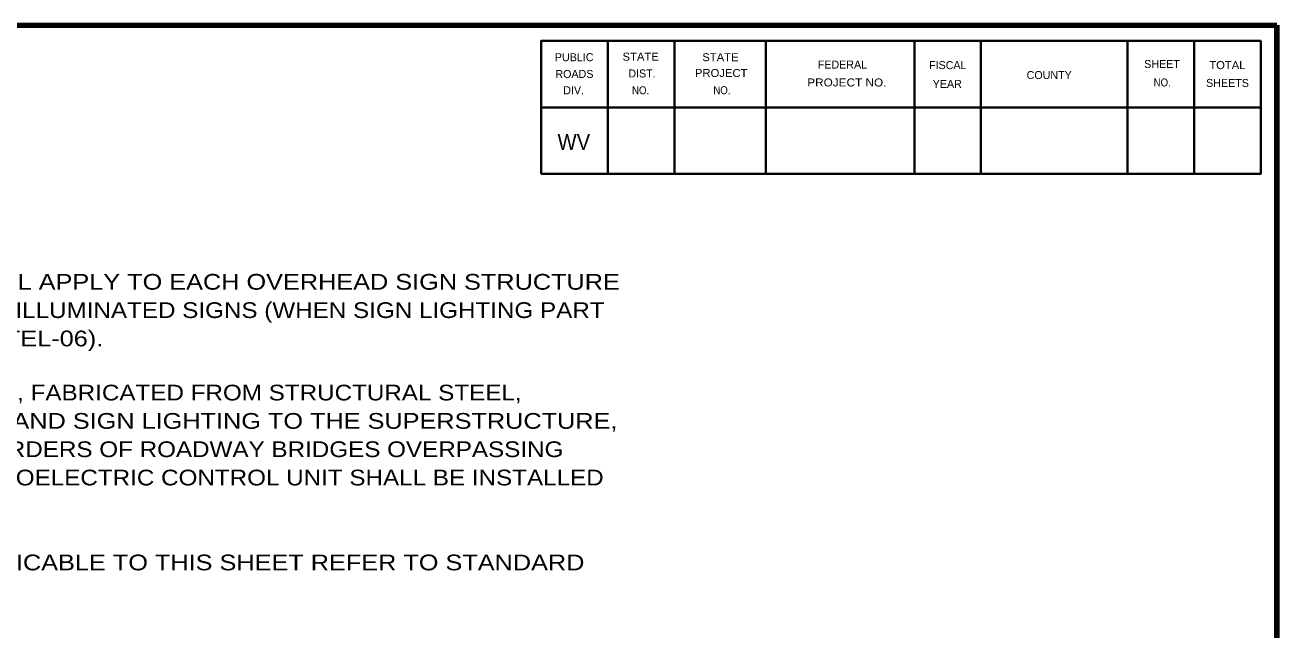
# Model space of a CAD drawing. Extents: x -111 to 744, y -77 to 467.
# Drawn here: x 499.2 to 737.7, y 344.9 to 460.3 of the extents above; entities that cross this region are included whole.
import ezdxf

# ---------------------------------------------------------------- set-up
doc = ezdxf.new("R2010")
doc.units = 0
doc.header["$LTSCALE"] = 1.2
doc.layers.add('1', color=7, linetype='Continuous', lineweight=53)
doc.layers.add('61', color=7, linetype='Continuous', lineweight=35)

msp = doc.modelspace()

# ---------------------------------------------------------------- linework, layer by layer
at = {"layer": '1', "lineweight": 158}
msp.add_line((737.728, -65.835), (737.728, 460.265), dxfattribs=at)
at = {"layer": '1', "lineweight": 13}
msp.add_line((737.728, -65.835), (737.728, 460.265), dxfattribs=at)
at = {"layer": '1', "lineweight": 158}
msp.add_lwpolyline([(737.728, 460.265), (-53.972, 460.165), (-53.872, -65.835)], dxfattribs=at)
at = {"layer": '61'}
for p, q in [((610.228, 457.265), (610.228, 431.865)), ((622.928, 457.265), (622.928, 431.865)), ((640.328, 457.265), (640.328, 431.865)), ((668.628, 457.265), (668.628, 431.865)), ((681.328, 457.265), (681.328, 431.865)), ((709.228, 457.265), (709.228, 431.865)), ((721.928, 457.265), (721.928, 431.865)), ((734.628, 444.565), (597.528, 444.565))]:
    msp.add_line(p, q, dxfattribs=at)
for points in [[(734.628, 457.265), (597.528, 457.265), (597.528, 431.865)], [(734.628, 457.265), (734.628, 431.865), (597.528, 431.865)]]:
    msp.add_lwpolyline(points, dxfattribs=at)

# ---------------------------------------------------------------- texts
at = {"layer": '1'}
for s, height, width, p in [('WV', 3.048, 0.95, (600.628, 436.465)), ('DETAILS OF THIS SHEET SHALL APPLY TO EACH OVERHEAD SIGN STRUCTURE', 3, 1.2, (426.063, 409.807)), ('THAT SUPPORTS EXTERNALLY ILLUMINATED SIGNS (WHEN SIGN LIGHTING PART', 3, 1.15, (426.063, 404.407)), ('OF ROADWAY LIGHTING SEE TEL-06).', 3, 1.2, (426.063, 399.007)), ('WHERE SPECIAL SIGN MOUNTS, FABRICATED FROM STRUCTURAL STEEL,', 3, 1.15, (425.89, 388.691)), ('ARE USED TO ATTACH SIGNS AND SIGN LIGHTING TO THE SUPERSTRUCTURE,', 3, 1.2, (425.89, 383.291)), ('PARAPET WALLS, OR PLATE GIRDERS OF ROADWAY BRIDGES OVERPASSING', 3, 1.15, (425.89, 377.891)), ('THE SIGNED ROUTE, THE PHOTOELECTRIC CONTROL UNIT SHALL BE INSTALLED', 3, 1.15, (425.89, 372.491)), ('FOR ADDITIONAL NOTES APPLICABLE TO THIS SHEET REFER TO STANDARD', 3, 1.2, (425.477, 356.304))]:
    msp.add_text(s, height=height, dxfattribs=dict(at, width=width)).set_placement(p)
at = {"layer": '61'}
for s, height, rotation, p in [('PUBLIC', 1.525, 0.033, (600.128, 453.365)), ('FEDERAL', 1.523, 0.007, (650.228, 451.965)), ('FISCAL', 1.525, 359.942, (671.428, 451.865)), ('SHEET', 1.525, 0.059, (712.428, 452.065)), ('ROADS', 1.525, 0.124, (600.228, 450.165)), ('DIST.', 1.525, 0.056, (614.128, 450.265)), ('COUNTY', 1.523, 0.069, (690.028, 449.965)), ('DIV.', 1.525, 359.932, (601.728, 447.065)), ('YEAR', 1.523, 0.105, (672.128, 448.265)), ('SHEETS', 1.523, 359.959, (724.228, 448.465))]:
    msp.add_text(s, height=height, rotation=rotation, dxfattribs=at).set_placement(p)
for s, rotation, width, p in [('STATE', 0.059, 1.05, (613.028, 453.465)), ('STATE', 0.059, 1.05, (628.228, 453.365)), ('TOTAL', 359.926, 1.05, (724.828, 451.865)), ('PROJECT', 359.908, 1.05, (626.828, 450.365)), ('NO.', 359.852, 0.9, (614.828, 447.065)), ('NO.', 0.225, 0.9, (630.328, 447.065)), ('PROJECT NO.', 359.922, 1.1, (648.228, 448.565)), ('NO.', 359.852, 0.9, (714.228, 448.565))]:
    msp.add_text(s, height=1.525, rotation=rotation, dxfattribs=dict(at, width=width)).set_placement(p)

doc.saveas('drawing.dxf')
